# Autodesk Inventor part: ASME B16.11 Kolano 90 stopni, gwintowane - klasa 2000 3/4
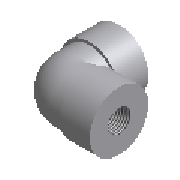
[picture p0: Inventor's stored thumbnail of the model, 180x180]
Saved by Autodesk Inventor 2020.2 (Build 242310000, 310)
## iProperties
Manager: www.cadconsulting.pl
Company: Fabian Stasiak CAD Consulting
NAME: PIPING: ASME B16.11 90 Deg Elbow Threaded - Class 2000
DATA: <meta><inlinegroups number="0" deflen="0"></inlinegroups><connections number="2"></connections><angles><a>1.57079632679489</a></angles></meta>
IsCustomPart: 0
Created: 2014-02
Part Number: ASME B16.11 Kolano 90 stopni, gwintowane - klasa 2000 3/4
Material: Stal
Description: Kolano 90º, kute, gwintowane - klasa 2000
Document SubType Name: Modeling
Standard: ASME B16.11
Designer: F.Stasiak
Standard Revision: 2005
Standards Organization: ANSI
Language: pl-PL
Size Designation: 3/4
Categories: <MemberInstance><Categories><Category DisplayName="Rury cienko- i grubościenne" InternalName="4347fa0f-2144-441d-94cd-e3e15c92b736" Mnemonic="TUBEANDPIPE"><Cate
Density: 1 g/cm^3
Appearance: Płyta
Catalog Web Link: www.expertbooks.pl
Author: F.Stasiak
Subject: Zbiór ćwiczeń. Autodesk Inventor 2020. Kurs Professional
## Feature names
1. Sweep1
2. Revolve1
3. Revolve2
4. Revolve3
5. Revolve4
6. Sweep2
## Parameters: MD = 23.66594 mm, A = 33.274 mm, L2 = 13.86078 mm, G = 3.175 mm, d0 = 23.66594 mm, d1 = 38.1 mm, d2 = 0.3124 mm, d3 = 0.3124 mm, d4 = 23.66594 mm, d5 = 38.1 mm, H = 38.1 mm, d6 = 13.86078 mm, d7 = 27.94 mm, d8 = 13.86078 mm, d9 = 27.94 mm, d10 = 0, d11 = 6.6548 mm, d12 = 6.6548 mm, d13 = 17.145 mm, d14 = 0, d101 = 90 deg, d102 = 90 deg, d105 = 25.4 mm, d106 = 0, d107 = 25.4 mm, d108 = 0, d15 = 33.274 mm, d16 = 18.3007 mm, d17 = 33.274 mm, d18 = 18.3007 mm, d19 = 34.29 mm, d20 = 34.29 mm, d21 = 6.6548 mm, d116 = 90 deg, d117 = 90 deg, d22 = 13.97003 mm, d23 = 0, d122 = 0, d123 = 0, Size_Designation = 7.5 mm
